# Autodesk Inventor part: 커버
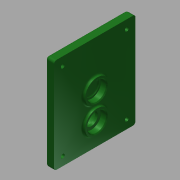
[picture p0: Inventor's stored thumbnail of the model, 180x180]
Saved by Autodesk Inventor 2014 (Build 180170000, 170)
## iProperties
Created: 2016-02
Part Number: 커버
Material: 알루미늄 6061
Document SubType Name: Modeling
Designer: mduedu
Density: 2.71 g/cm^3
Mass: 272.254 g
Surface Area: 266.629 cm^2
Volume: 100.463 cm^3
Appearance: 매끄러움 - 짙은 산림 녹색
Author: mduedu
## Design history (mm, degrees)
sketch "스케치1"
  geometry: L1 (63, 47)-(-47, 47); L2 (-47, 47)-(-47, -47); L3 (-47, -47)-(63, -47); L4 (63, -47)-(63, 47); 2 further points
  constraints: 8 end point, 2 parallel, 1 horizontal, 1 horizontal alignment, 1 midpoint, 1 perpendicular
  dimensions: "d102" = 94 distance of L3.end L1.start; "d104" = 47 distance from line of L2 point (0, 0); "d105" = 110 distance of L1.start L1.end
extrude "돌출1" new body sketch "스케치1" distance "d1" = 10; taper "d2" = 0 deg
sketch "스케치2"
  geometry: C1 r 14 at (0, 11); 1 further point
  constraints: 1 centre point, 1 vertical alignment
  dimensions: "d3" = 28 diameter of C1; "d6" = 11 distance of C1.centre point (0, 0)
extrude "돌출2" join sketch "스케치2" distance "d7" = 3; taper "d8" = 0 deg
sketch "스케치3"
  geometry: C1 r 14 at (0, -20); 1 further point
  constraints: 1 centre point, 1 vertical alignment
  dimensions: "d9" = 28 diameter of C1; "d10" = 20 distance of C1.centre point (0, 0)
extrude "돌출3" join sketch "스케치3" distance "d11" = 3; taper "d12" = 0 deg
hole "구멍1" diameter "d15" = 22; stored, may be unused: countersink angle "d19" = 90 deg, drill point angle "d21" = 0 deg; dims "d13" = 10, "d14" = 10, "d16" = 6, "d17" = 4, "d18" = 2, "d20" = 7
hole "구멍2" diameter "d24" = 18; stored, may be unused: countersink angle "d28" = 90 deg, drill point angle "d30" = 0 deg; dims "d22" = 10, "d23" = 10, "d25" = 6, "d26" = 4, "d27" = 2, "d29" = 1
hole "구멍3" diameter "d33" = 22; stored, may be unused: countersink angle "d37" = 90 deg, drill point angle "d39" = 0 deg; dims "d34" = 6, "d35" = 4, "d36" = 2, "d38" = 7, "d73" = 10, "d74" = 10
sketch "스케치4"
  geometry: C1 r 14 at (0, -20) reference; C2 r 18 at (0, -20); 1 further point
  constraints: 1 centre point, 1 coincident
  dimensions: "d40" = 36 diameter of C2
extrude "돌출4" join sketch "스케치4" distance "d41" = 4; taper "d42" = 0 deg
hole "구멍4" diameter "d45" = 22; stored, may be unused: countersink angle "d49" = 90 deg, drill point angle "d51" = 0 deg; dims "d43" = 10, "d44" = 10, "d46" = 6, "d47" = 4, "d48" = 2, "d50" = 7
hole "구멍5" diameter "d54" = 15; stored, may be unused: countersink angle "d58" = 90 deg, drill point angle "d60" = 0 deg; dims "d52" = 10, "d53" = 10, "d55" = 6, "d56" = 4, "d57" = 2, "d59" = 7
fillet "모깎기1" dims "d61" = 0.3
fillet "모깎기2" dims "d62" = 2
chamfer "모따기1" distance "d63" = 1; stored, may be unused: second distance "d64" = 2, angle "d65" = 45 deg
fillet "모깎기6" dims "d88" = 2
fillet "모깎기4" dims "d75" = 2
sketch "스케치9"
  geometry: L1 (47, 63)-(47, -47) reference; L2 (-47, 63)-(47, 63) reference; L3 (-47, -47)-(-47, 63) reference; L4 (47, -47)-(-47, -47) reference; L5 (37, 53)-(37, -37); L6 (37, -37)-(-37, -37); L7 (-37, -37)-(-37, 53); L8 (-37, 53)-(37, 53); C1 r 20 at (0, -20) reference; 5 further points
  constraints: 8 end point, 4 coincident, 3 other
  dimensions: "d107" = 10 distance between parallel lines of L8 L2
hole "구멍7" sketch "스케치9" at (-37, 53), (37, 53), (37, -37), (-37, -37) diameter "d108" = 4.5; stored, may be unused: countersink angle "d112" = 90 deg, drill point angle "d114" = 118 deg; dims "d109" = 6, "d110" = 8, "d111" = 4.6, "d113" = 8
fillet "모깎기8" dims "d106" = 3
fillet "모깎기9" dims "d115" = 3
node "솔리드1"
node "투영된 루프2"
